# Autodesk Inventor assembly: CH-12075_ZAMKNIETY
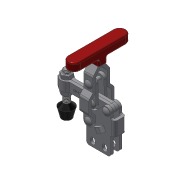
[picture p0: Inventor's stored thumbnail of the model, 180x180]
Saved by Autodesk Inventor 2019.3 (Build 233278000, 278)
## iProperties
Company: Î¢ÈíÖÐ¹ú
Created: 2015-08
Part Number: CH-12075_ZAMKNIETY
Material: Ogólny
Description: STEP AP203
Document SubType Name: Assembly
Designer: CADENGINEERING4
Sending System: SolidWorks 2012
Preprocessor: SwSTEP 2.0
Title: CH-12075.STEP
Author: Î¢ÈíÓÃ»§
Revision Number: ÈÎºÎ
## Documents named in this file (9)
- D:\Vault_2016\Projekty\NASZ KATALOG\CLAMPTEK\STRONA\Vertical toggle clamp\CH-12075\CH-12075_ZAMKNIETY.iam
- D:\Vault_2016\Projekty\NASZ KATALOG\CLAMPTEK\STEP FILES\Vertical toggle clamp\CH-12075\CH-12055-01 STRAIGHT BASE.ipt
- D:\Vault_2016\Projekty\NASZ KATALOG\CLAMPTEK\STEP FILES\Vertical toggle clamp\CH-12075\CH-12075-02 FIXED SPINDLE.ipt
- D:\Vault_2016\Projekty\NASZ KATALOG\CLAMPTEK\STEP FILES\Vertical toggle clamp\CH-12075\CH-12070-03 T-HANDLE.ipt
- D:\Vault_2016\Projekty\NASZ KATALOG\CLAMPTEK\STEP FILES\Vertical toggle clamp\CH-12075\CH-12050-07.ipt
- D:\Vault_2016\Projekty\NASZ KATALOG\CLAMPTEK\STEP FILES\Vertical toggle clamp\CH-12075\CH-12050-06.ipt
- D:\Vault_2016\Projekty\NASZ KATALOG\CLAMPTEK\STEP FILES\Vertical toggle clamp\CH-12075\CH-12050-04 CONNECTING-PLATE.ipt
- D:\Vault_2016\Projekty\NASZ KATALOG\CLAMPTEK\STEP FILES\Vertical toggle clamp\CH-12075\CH-FC-14134 Nut.ipt
- D:\Vault_2016\Projekty\NASZ KATALOG\CLAMPTEK\STEP FILES\Vertical toggle clamp\CH-12075\CH-FC-14134 SPINDLE SUPPLIED.ipt
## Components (11 placed, 11 different names)
1. CH-12055-01 STRAIGHT BASE_1
2. CH-12075-02 FIXED SPINDLE_2
3. CH-12070-03 T-HANDLE_3
4. CH-12050-07_4
5. CH-12050-07_5
6. CH-12050-06_6
7. CH-12050-04 CONNECTING-PLATE_7
8. CH-12050-06_8
9. CH-FC-14134 Nut_9
10. CH-FC-14134 SPINDLE SUPPLIED_10
11. CH-FC-14134 Nut_11
